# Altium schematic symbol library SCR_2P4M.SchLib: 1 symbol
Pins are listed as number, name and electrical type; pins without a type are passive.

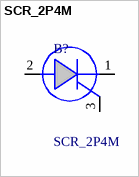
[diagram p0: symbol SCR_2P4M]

## SCR_2P4M
designator B?
Plastic Moulded Thyristor; Manufacturer_Name: NEC; Manufacturer_Part_Number: SCR 2P4M; Geometry.Height: 4.7mm
footprint TO255P470X1000X2380-3P
pins: 1 K, 2 A, 3 G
